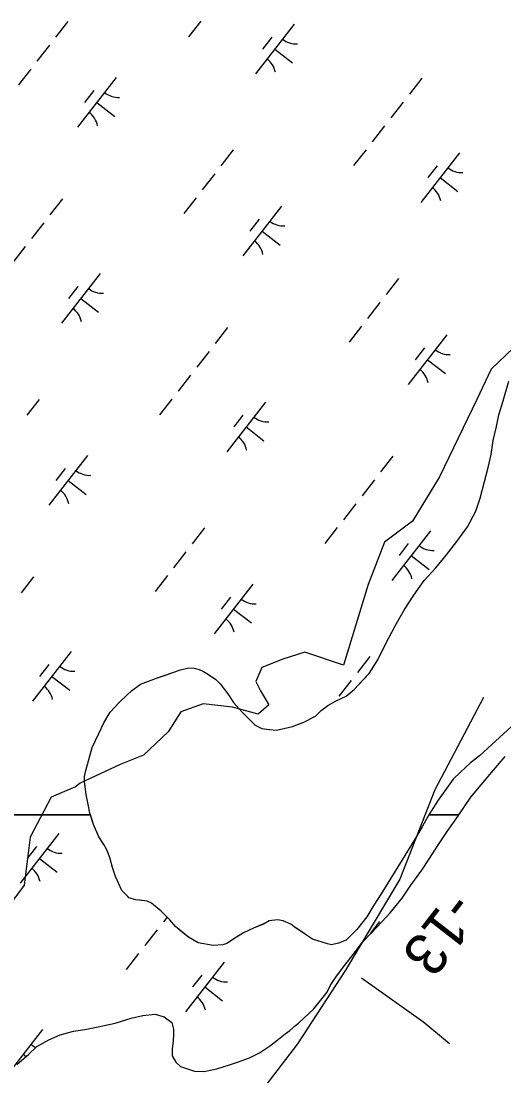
# Model space of a CAD drawing. Extents: x 3888273 to 3909528, y 158682 to 181032.
# Drawn here: x 3900588 to 3900971, y 172716 to 173553 of the extents above; entities that cross this region are included whole.
import ezdxf

# ---------------------------------------------------------------- set-up
doc = ezdxf.new("R2010")
doc.units = 0
for name, color, linetype in [('V-LEVE-TOET', 7, 'Continuous'), ('V-RIVR-EDGE', 7, 'Continuous'), ('V-RIVR-RANG', 7, 'Continuous'), ('V-RRAP-FSHR', 7, 'Continuous'), ('V-TOPO-SHOR', 7, 'Continuous'), ('V-WETL-SWMP', 7, 'Continuous')]:
    doc.layers.add(name, color=color, linetype=linetype)

msp = doc.modelspace()

# ---------------------------------------------------------------- linework, layer by layer
at = {"layer": 'V-LEVE-TOET'}
msp.add_lwpolyline([(3900928.12, 172740.98), (3900907.67, 172757.86), (3900858.02, 172793.11)], dxfattribs=at)
at = {"layer": 'V-RIVR-EDGE'}
msp.add_lwpolyline([(3900978.64, 173293.65), (3900960.99, 173276.93), (3900949.84, 173252.77), (3900920.1, 173191.44), (3900898.73, 173156.13), (3900876.43, 173139.4), (3900863.42, 173105.95), (3900843.91, 173041.84), (3900813.24, 173052.06), (3900795.59, 173046.48), (3900778.86, 173039.98), (3900774.22, 173028.83), (3900777.93, 173021.4), (3900784.44, 173010.24), (3900776.07, 173002.81), (3900755.63, 173008.39), (3900732.4, 173011.17), (3900714.75, 173004.67), (3900704.52, 172988.87), (3900685.01, 172970.29), (3900666.43, 172962.86), (3900634.83, 172947.99), (3900631.12, 172945.2), (3900611.6, 172936.84), (3900594.88, 172905.24), (3900590.23, 172867.15), (3900552.13, 172816.04)], dxfattribs=at)
at = {"layer": 'V-RRAP-FSHR'}
msp.add_lwpolyline([(3900954.94, 173016.13), (3900916.45, 172942.7), (3900888.67, 172871.74), (3900845.5, 172799.4), (3900807.26, 172740.91), (3900720.01, 172626.92)], dxfattribs=at)
at = {"layer": 'V-TOPO-SHOR'}
for points in [[(3900639.15, 172958.02), (3900644.14, 172976.39), (3900649.6, 172987.6), (3900653.49, 172996.01), (3900658.58, 173004.42), (3900665.67, 173012.07), (3900671.98, 173018.11), (3900675.53, 173021.33), (3900682.64, 173026.58), (3900688.99, 173029.04), (3900695.34, 173031.49), (3900702.48, 173033.96), (3900708.43, 173036.01), (3900714.39, 173038.07), (3900721.14, 173039.73), (3900725.13, 173039.38), (3900729.12, 173038.22), (3900732.72, 173036.67), (3900736.73, 173034.32), (3900742.35, 173030.39), (3900745.97, 173026.85), (3900752.02, 173018.95), (3900756.48, 173012.22), (3900763.33, 173004.33), (3900767.76, 172999.99), (3900773.79, 172994.08), (3900779, 172991.35), (3900784.98, 172990.61), (3900790.56, 172990.27), (3900796.52, 172991.53), (3900803.27, 172993.2), (3900812.4, 172996.48), (3900821.51, 173001.35), (3900826.24, 173005.78), (3900831.38, 173009.82), (3900838.11, 173013.48), (3900846.04, 173017.14), (3900852.35, 173022.39), (3900857.87, 173028.42), (3900864.17, 173035.26), (3900871.23, 173046.08), (3900877.07, 173058.49), (3900884.88, 173072.91), (3900892.31, 173086.13), (3900899.76, 173097.36), (3900908, 173109), (3900917.06, 173119.05), (3900925.71, 173129.5), (3900933.96, 173139.94), (3900942.21, 173151.58), (3900948.85, 173163.99), (3900952.32, 173174.39), (3900955.77, 173187.56), (3900958.84, 173198.75), (3900961.12, 173209.13), (3900962.59, 173220.3), (3900965.27, 173231.47), (3900967.16, 173240.65), (3900970.63, 173251.84), (3900975.24, 173267.42)], [(3900977.09, 172992.79), (3900961.7, 172978.69), (3900951.84, 172969.82), (3900944.73, 172964.17), (3900936.84, 172956.92), (3900930.92, 172951.28), (3900927, 172945.67), (3900919.15, 172934.43), (3900911.71, 172922.8), (3900906.62, 172913.99), (3900901.93, 172905.58), (3900898.01, 172899.56), (3900873.73, 172860.27), (3900867.85, 172851.05), (3900862.38, 172841.83), (3900854.51, 172831.79), (3900845.84, 172823.34), (3900839.89, 172820.89), (3900834.33, 172819.63), (3900831.14, 172820.4), (3900819.15, 172824.25), (3900814.33, 172827.39), (3900811.53, 172829.35), (3900804.71, 172834.06)], [(3900804.71, 172834.06), (3900801.9, 172836.02), (3900795.89, 172838.75), (3900791.5, 172839.5), (3900784.74, 172838.63), (3900780.39, 172836.2), (3900772.46, 172832.92), (3900764.53, 172829.26), (3900760.18, 172826.42), (3900758.99, 172825.61), (3900751.08, 172820.75), (3900747.91, 172819.52), (3900740.34, 172819.05), (3900728.37, 172821.31), (3900720.76, 172825.61), (3900715.94, 172829.54), (3900710.31, 172834.26), (3900705.88, 172839.4), (3900699.03, 172846.49), (3900691.4, 172852.78), (3900687.8, 172854.34), (3900681.82, 172855.07), (3900679.02, 172855.44), (3900673.43, 172856.98), (3900672.62, 172858.16), (3900667.79, 172862.89), (3900662.9, 172873.99), (3900660.43, 172881.14), (3900658.36, 172889.08), (3900655.91, 172895.03), (3900653.47, 172899.38), (3900649.42, 172905.32), (3900645.34, 172915.23), (3900642.46, 172924.36), (3900641.19, 172931.12), (3900639.51, 172939.07), (3900638.65, 172945.43), (3900638.21, 172949.01), (3900638.17, 172953.39), (3900639.15, 172958.02)]]:
    msp.add_lwpolyline(points, dxfattribs=at)
at = {"layer": 'V-WETL-SWMP'}
for p, q in [((3900625, 173553.14), (3900615.17, 173540.51)), ((3900730.46, 173553.38), (3900720.63, 173540.76)), ((3900804.6, 173550.91), (3900773.9, 173511.45)), ((3900786.84, 173540.65), (3900779.48, 173531.18)), ((3900610.26, 173534.2), (3900600.43, 173521.57)), ((3900789.25, 173531.18), (3900803.46, 173520.13)), ((3900595.52, 173515.26), (3900585.69, 173502.63)), ((3900663.36, 173508.46), (3900632.66, 173469)), ((3900905.95, 173508.07), (3900896.13, 173495.44)), ((3900645.6, 173498.2), (3900638.23, 173488.73)), ((3900648.01, 173488.73), (3900662.21, 173477.68)), ((3900891.22, 173489.12), (3900881.39, 173476.5)), ((3900876.48, 173470.18), (3900866.65, 173457.55)), ((3900756.28, 173451), (3900746.45, 173438.37)), ((3900861.74, 173451.24), (3900851.91, 173438.61)), ((3900935.88, 173448.77), (3900905.18, 173409.3)), ((3900918.13, 173438.51), (3900910.76, 173429.04)), ((3900741.54, 173432.06), (3900731.71, 173419.43)), ((3900920.53, 173429.04), (3900934.74, 173417.98)), ((3900620.57, 173412.15), (3900610.74, 173399.52)), ((3900726.8, 173413.11), (3900716.98, 173400.49)), ((3900794.64, 173406.32), (3900763.94, 173366.86)), ((3900776.88, 173396.06), (3900769.52, 173386.59)), ((3900605.83, 173393.2), (3900596, 173380.58)), ((3900779.29, 173386.59), (3900793.5, 173375.53)), ((3900591.09, 173374.26), (3900581.27, 173361.63)), ((3900650.5, 173352.85), (3900619.79, 173313.39)), ((3900887.56, 173348.85), (3900877.73, 173336.22)), ((3900632.74, 173342.59), (3900625.37, 173333.12)), ((3900635.14, 173333.12), (3900649.35, 173322.06)), ((3900872.82, 173329.91), (3900862.99, 173317.28)), ((3900858.08, 173310.97), (3900848.26, 173298.34)), ((3900751.85, 173310), (3900742.02, 173297.37)), ((3900925.92, 173304.17), (3900895.22, 173264.71)), ((3900908.16, 173293.92), (3900900.8, 173284.44)), ((3900737.11, 173291.06), (3900727.28, 173278.43)), ((3900910.57, 173284.44), (3900924.78, 173273.39)), ((3900722.37, 173272.12), (3900712.55, 173259.49)), ((3900970.63, 173251.84), (3900975.24, 173267.42)), ((3900602.17, 173252.93), (3900592.34, 173240.31)), ((3900707.63, 173253.18), (3900697.81, 173240.55)), ((3900967.16, 173240.65), (3900970.63, 173251.84)), ((3900781.78, 173250.7), (3900751.07, 173211.24)), ((3900764.02, 173240.45), (3900756.65, 173230.97)), ((3900965.27, 173231.47), (3900967.16, 173240.65)), ((3900766.42, 173230.97), (3900780.63, 173219.92)), ((3900962.59, 173220.3), (3900965.27, 173231.47)), ((3900961.12, 173209.13), (3900962.59, 173220.3)), ((3900640.53, 173208.25), (3900609.83, 173168.79)), ((3900883.13, 173207.86), (3900873.3, 173195.23)), ((3900958.84, 173198.75), (3900961.12, 173209.13)), ((3900622.78, 173198), (3900615.41, 173188.53)), ((3900955.77, 173187.56), (3900958.84, 173198.75)), ((3900625.18, 173188.52), (3900639.39, 173177.47)), ((3900868.39, 173188.91), (3900858.56, 173176.29)), ((3900952.32, 173174.39), (3900955.77, 173187.56)), ((3900853.65, 173169.97), (3900843.83, 173157.35)), ((3900948.85, 173163.99), (3900952.32, 173174.39)), ((3900942.21, 173151.58), (3900948.85, 173163.99)), ((3900838.91, 173151.03), (3900829.09, 173138.4)), ((3900933.96, 173139.94), (3900942.21, 173151.58)), ((3900733.45, 173150.79), (3900723.63, 173138.16)), ((3900913.06, 173148.56), (3900882.35, 173109.1)), ((3900895.3, 173138.3), (3900887.93, 173128.83)), ((3900925.71, 173129.5), (3900933.96, 173139.94)), ((3900718.71, 173131.85), (3900708.89, 173119.22)), ((3900897.7, 173128.83), (3900911.91, 173117.77)), ((3900917.06, 173119.05), (3900925.71, 173129.5)), ((3900908, 173109), (3900917.06, 173119.05)), ((3900597.74, 173111.94), (3900587.92, 173099.31)), ((3900703.98, 173112.91), (3900694.15, 173100.28)), ((3900771.82, 173106.11), (3900741.11, 173066.65)), ((3900899.76, 173097.36), (3900908, 173109)), ((3900754.06, 173095.85), (3900746.69, 173086.38)), ((3900892.31, 173086.13), (3900899.76, 173097.36)), ((3900756.46, 173086.38), (3900770.67, 173075.32)), ((3900884.88, 173072.91), (3900892.31, 173086.13)), ((3900877.07, 173058.49), (3900884.88, 173072.91)), ((3900627.67, 173052.64), (3900596.97, 173013.18)), ((3900871.22, 173046.08), (3900877.07, 173058.49)), ((3900609.91, 173042.38), (3900602.54, 173032.91)), ((3900864.73, 173048.64), (3900854.91, 173036.02)), ((3900864.17, 173035.26), (3900871.22, 173046.08)), ((3900695.34, 173031.49), (3900714.39, 173038.07)), ((3900714.39, 173038.07), (3900721.14, 173039.73)), ((3900721.14, 173039.73), (3900725.13, 173039.37)), ((3900725.13, 173039.37), (3900729.12, 173038.22)), ((3900729.12, 173038.22), (3900732.72, 173036.67)), ((3900732.72, 173036.67), (3900736.73, 173034.32)), ((3900736.73, 173034.32), (3900742.35, 173030.39)), ((3900852.35, 173022.39), (3900864.17, 173035.26)), ((3900612.32, 173032.91), (3900626.52, 173021.85)), ((3900675.53, 173021.33), (3900682.64, 173026.58)), ((3900682.64, 173026.58), (3900695.34, 173031.49)), ((3900742.35, 173030.39), (3900745.97, 173026.85)), ((3900745.97, 173026.85), (3900752.02, 173018.95)), ((3900849.99, 173029.7), (3900840.17, 173017.07)), ((3900665.67, 173012.07), (3900671.98, 173018.11)), ((3900671.98, 173018.11), (3900675.53, 173021.33)), ((3900752.02, 173018.95), (3900756.48, 173012.22)), ((3900838.11, 173013.48), (3900846.04, 173017.14)), ((3900846.04, 173017.14), (3900852.35, 173022.39)), ((3900658.58, 173004.42), (3900665.67, 173012.07)), ((3900756.48, 173012.22), (3900763.33, 173004.33)), ((3900826.24, 173005.78), (3900831.38, 173009.82)), ((3900831.38, 173009.82), (3900838.11, 173013.48)), ((3900653.49, 172996.01), (3900658.58, 173004.42)), ((3900763.33, 173004.33), (3900773.79, 172994.08)), ((3900812.4, 172996.48), (3900821.51, 173001.35)), ((3900821.51, 173001.35), (3900826.24, 173005.78)), ((3900649.6, 172987.6), (3900653.49, 172996.01)), ((3900773.79, 172994.08), (3900779, 172991.35)), ((3900796.52, 172991.53), (3900803.27, 172993.2)), ((3900803.27, 172993.2), (3900812.4, 172996.48)), ((3900977.09, 172992.79), (3900961.7, 172978.69)), ((3900644.14, 172976.39), (3900649.6, 172987.6)), ((3900779, 172991.35), (3900784.98, 172990.61)), ((3900784.98, 172990.61), (3900790.56, 172990.28)), ((3900790.56, 172990.28), (3900796.52, 172991.53)), ((3900639.15, 172958.02), (3900644.14, 172976.39)), ((3900961.7, 172978.69), (3900951.84, 172969.82)), ((3900951.84, 172969.82), (3900944.73, 172964.17)), ((3900962.98, 172958.42), (3900972.37, 172969.22)), ((3900944.73, 172964.17), (3900936.84, 172956.92)), ((3900953.2, 172946.83), (3900962.98, 172958.42)), ((3900638.17, 172953.39), (3900639.15, 172958.02)), ((3900638.21, 172949.01), (3900638.17, 172953.39)), ((3900930.93, 172951.28), (3900919.15, 172934.43)), ((3900936.84, 172956.92), (3900930.93, 172951.28)), ((3900639.51, 172939.07), (3900638.21, 172949.01)), ((3900944.98, 172936.84), (3900953.2, 172946.83)), ((3900641.19, 172931.12), (3900639.51, 172939.07)), ((3900919.15, 172934.43), (3900911.72, 172922.82)), ((3900935.46, 172922.82), (3900944.98, 172936.84)), ((3900642.46, 172924.36), (3900641.19, 172931.12)), ((3899441.76, 172922.82), (3900642.94, 172922.82)), ((3900642.94, 172922.82), (3899441.76, 172922.82)), ((3900642.94, 172922.82), (3900642.46, 172924.36)), ((3900645.34, 172915.23), (3900642.94, 172922.82)), ((3900911.71, 172922.8), (3900906.62, 172913.99)), ((3900911.72, 172922.82), (3900911.71, 172922.8)), ((3900911.72, 172922.82), (3900935.46, 172922.82)), ((3900935.46, 172922.82), (3900911.72, 172922.82)), ((3900926.25, 172909.71), (3900935.23, 172922.48)), ((3900935.23, 172922.48), (3900935.46, 172922.82)), ((3900617.71, 172908.05), (3900587.01, 172868.58)), ((3900649.43, 172905.32), (3900645.34, 172915.23)), ((3900906.62, 172913.99), (3900901.93, 172905.58)), ((3900918.84, 172898.53), (3900926.25, 172909.71)), ((3900653.47, 172899.38), (3900649.43, 172905.32)), ((3900898.01, 172899.56), (3900873.73, 172860.27)), ((3900901.93, 172905.58), (3900898.01, 172899.56)), ((3900599.95, 172897.79), (3900592.58, 172888.32)), ((3900655.91, 172895.03), (3900653.47, 172899.38)), ((3900658.36, 172889.08), (3900655.91, 172895.03)), ((3900912.21, 172888.16), (3900918.84, 172898.53)), ((3900602.36, 172888.31), (3900616.56, 172877.26)), ((3900660.43, 172881.14), (3900658.36, 172889.08)), ((3900905.97, 172878.99), (3900912.21, 172888.16)), ((3900662.9, 172873.99), (3900660.43, 172881.14)), ((3900897.38, 172867.01), (3900905.97, 172878.99)), ((3900667.79, 172862.89), (3900662.9, 172873.99)), ((3900890.36, 172856.64), (3900897.38, 172867.01)), ((3900672.62, 172858.16), (3900667.79, 172862.89)), ((3900673.43, 172856.98), (3900672.62, 172858.16)), ((3900873.73, 172860.27), (3900867.85, 172851.05)), ((3900679.02, 172855.44), (3900673.43, 172856.98)), ((3900687.8, 172854.34), (3900679.02, 172855.44)), ((3900691.4, 172852.78), (3900687.8, 172854.34)), ((3900699.03, 172846.49), (3900691.4, 172852.78)), ((3900867.85, 172851.05), (3900862.38, 172841.83)), ((3900880.97, 172845.05), (3900890.36, 172856.64)), ((3900705.88, 172839.39), (3900699.03, 172846.49)), ((3900703.69, 172841.66), (3900700.8, 172837.95)), ((3900862.38, 172841.83), (3900854.51, 172831.79)), ((3900874.31, 172837.85), (3900880.97, 172845.05)), ((3900710.31, 172834.26), (3900705.88, 172839.39)), ((3900720.76, 172825.61), (3900710.31, 172834.26)), ((3900772.46, 172832.92), (3900764.53, 172829.26)), ((3900780.39, 172836.19), (3900772.46, 172832.92)), ((3900784.74, 172838.63), (3900780.39, 172836.19)), ((3900791.5, 172839.5), (3900784.74, 172838.63)), ((3900795.89, 172838.75), (3900791.5, 172839.5)), ((3900801.9, 172836.02), (3900795.89, 172838.75)), ((3900804.71, 172834.06), (3900801.9, 172836.02)), ((3900814.33, 172827.39), (3900804.71, 172834.06)), ((3900872.47, 172838.09), (3900865.11, 172828.62)), ((3900866.48, 172829.45), (3900874.31, 172837.85)), ((3900695.89, 172831.64), (3900686.06, 172819.01)), ((3900728.37, 172821.31), (3900720.76, 172825.61)), ((3900758.99, 172825.61), (3900751.08, 172820.75)), ((3900764.53, 172829.26), (3900758.99, 172825.61)), ((3900819.15, 172824.25), (3900814.33, 172827.39)), ((3900831.14, 172820.4), (3900819.15, 172824.25)), ((3900854.51, 172831.79), (3900845.84, 172823.34)), ((3900858.64, 172821.44), (3900866.48, 172829.45)), ((3900740.34, 172819.05), (3900728.37, 172821.31)), ((3900747.9, 172819.52), (3900740.34, 172819.05)), ((3900751.08, 172820.75), (3900747.9, 172819.52)), ((3900834.33, 172819.63), (3900831.14, 172820.4)), ((3900839.89, 172820.89), (3900834.33, 172819.63)), ((3900845.84, 172823.34), (3900839.89, 172820.89)), ((3900851.61, 172811.86), (3900858.64, 172821.44)), ((3900681.15, 172812.7), (3900671.32, 172800.07)), ((3900844.96, 172803.47), (3900851.61, 172811.86)), ((3900748.99, 172805.9), (3900718.29, 172766.44)), ((3900838.32, 172794.69), (3900844.96, 172803.47)), ((3900731.23, 172795.64), (3900723.86, 172786.17)), ((3900833.64, 172787.51), (3900838.32, 172794.69)), ((3900733.64, 172786.17), (3900747.84, 172775.12)), ((3900830.92, 172781.93), (3900833.64, 172787.51)), ((3900820.37, 172768.75), (3900830.92, 172781.93)), ((3900808.2, 172757.53), (3900820.37, 172768.75)), ((3900649.02, 172754.45), (3900662.53, 172757.38)), ((3900662.53, 172757.38), (3900675.23, 172761.49)), ((3900675.23, 172761.49), (3900684.37, 172763.58)), ((3900684.37, 172763.58), (3900694.32, 172764.48)), ((3900694.32, 172764.48), (3900701.51, 172762.57)), ((3900701.51, 172762.57), (3900707.53, 172757.85)), ((3900707.53, 172757.85), (3900708.78, 172752.69)), ((3900805.7, 172755.56), (3900808.2, 172757.53)), ((3900604.84, 172752.43), (3900581.72, 172722.71)), ((3900618.81, 172748.16), (3900629.54, 172751.06)), ((3900629.54, 172751.06), (3900638.29, 172752.35)), ((3900638.29, 172752.35), (3900649.02, 172754.45)), ((3900708.78, 172752.69), (3900708.82, 172748.7)), ((3900790.92, 172743.59), (3900797.64, 172748.84)), ((3900797.64, 172748.84), (3900801.19, 172751.66)), ((3900801.19, 172751.66), (3900805.7, 172755.56)), ((3900600.19, 172738.8), (3900609.7, 172744.08)), ((3900609.7, 172744.08), (3900618.81, 172748.16)), ((3900708.48, 172743.12), (3900707.75, 172737.14)), ((3900708.82, 172748.7), (3900708.48, 172743.12)), ((3900784.99, 172739.15), (3900790.92, 172743.59)), ((3900584.41, 172724.7), (3900593.89, 172732.76)), ((3900589.49, 172732.7), (3900591.75, 172730.94)), ((3900593.89, 172732.76), (3900600.19, 172738.8)), ((3900707.75, 172737.14), (3900707.81, 172731.57)), ((3900769.16, 172729.82), (3900777.08, 172733.89)), ((3900777.08, 172733.89), (3900784.99, 172739.15)), ((3900707.81, 172731.57), (3900710.65, 172726.42)), ((3900710.65, 172726.42), (3900714.27, 172722.87)), ((3900743.36, 172721.19), (3900754.08, 172724.49)), ((3900754.08, 172724.49), (3900759.64, 172726.53)), ((3900759.64, 172726.53), (3900769.16, 172729.82)), ((3900714.27, 172722.87), (3900725.46, 172719.41)), ((3900725.46, 172719.41), (3900733.03, 172719.09)), ((3900733.03, 172719.09), (3900743.36, 172721.19))]:
    msp.add_line(p, q, dxfattribs=at)
for centre, start, end in [((3900806.4, 173552.83), 231.34298, 272.88664), ((3900772.48, 173509.23), 11.34298, 52.88663), ((3900665.16, 173510.39), 231.34298, 272.88664), ((3900631.23, 173466.79), 11.34298, 52.88663), ((3900937.68, 173450.69), 231.34298, 272.88664), ((3900903.76, 173407.09), 11.34298, 52.88663), ((3900796.44, 173408.24), 231.34298, 272.88664), ((3900762.51, 173364.64), 11.34298, 52.88663), ((3900652.29, 173354.77), 231.34298, 272.88664), ((3900618.37, 173311.17), 11.34298, 52.88663), ((3900927.72, 173306.1), 231.34298, 272.88664), ((3900893.8, 173262.5), 11.34298, 52.88663), ((3900783.57, 173252.63), 231.34298, 272.88664), ((3900749.65, 173209.03), 11.34298, 52.88663), ((3900642.33, 173210.18), 231.34298, 272.88664), ((3900608.41, 173166.58), 11.34298, 52.88663), ((3900914.85, 173150.48), 231.34298, 272.88664), ((3900880.93, 173106.88), 11.34298, 52.88663), ((3900773.61, 173108.03), 231.34298, 272.88664), ((3900739.69, 173064.43), 11.34298, 52.88663), ((3900629.47, 173054.56), 231.34298, 272.88664), ((3900595.54, 173010.96), 11.34298, 52.88663), ((3900619.51, 172909.97), 231.34298, 272.88664), ((3900585.58, 172866.37), 11.34298, 52.88663), ((3900750.79, 172807.82), 231.34298, 272.88664), ((3900716.86, 172764.22), 11.34298, 52.88663), ((3900606.64, 172754.35), 231.34298, 246.36157)]:
    msp.add_arc(centre, 17.62, start, end, dxfattribs=at)

# ---------------------------------------------------------------- texts
at = {"layer": 'V-RIVR-RANG'}
msp.add_text('-13', height=33.5, rotation=232.15833, dxfattribs=at).set_placement((3900928.59, 172863.66))

doc.saveas('drawing.dxf')
